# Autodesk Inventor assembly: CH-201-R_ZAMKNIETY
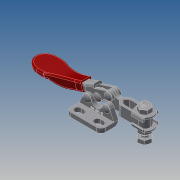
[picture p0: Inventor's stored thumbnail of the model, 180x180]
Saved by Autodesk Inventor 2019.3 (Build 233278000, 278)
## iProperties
Company: ·L?¤¤?
Created: 2010-06
Part Number: CH-201-R_ZAMKNIETY
Material: Ogólny
Description: STEP AP203
Document SubType Name: Assembly
Designer: CADENGINEERING4
Sending System: SolidWorks 2005179
Preprocessor: SwSTEP 2.0
Title: CH-201-R.STEP
Author: ·L?¥Î?
Revision Number: ANY
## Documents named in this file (9)
- E:\STRONA\Horizontal toggle clamp\CH-201-R\CH-201-R_ZAMKNIETY.iam
- E:\STRONA\Horizontal toggle clamp\CH-201-R\201-02___.ipt
- E:\STRONA\Horizontal toggle clamp\CH-201-R\201-06___.ipt
- E:\STRONA\Horizontal toggle clamp\CH-201-R\CH-SA-042007___.ipt
- E:\STRONA\Horizontal toggle clamp\CH-201-R\M4___.ipt
- E:\STRONA\Horizontal toggle clamp\CH-201-R\201-A-04___.ipt
- E:\STRONA\Horizontal toggle clamp\CH-201-R\CH-FW-080___.ipt
- E:\STRONA\Horizontal toggle clamp\CH-201-R\201-R-01___.ipt
- E:\STRONA\Horizontal toggle clamp\CH-201-R\201-03___.iam
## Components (14 placed, 14 different names)
1. 201-02_??_1 — Równoległe:1, Zestawiające:5, Zestawiające:7, Zestawiające:9, Zestawiające:25, Zestawiające:26, Zestawiające:27
2. 201-06_??_2 — Zestawiające:19, Zestawiające:20
3. CH-SA-042007_??_3 — Równoległe:2, Zestawiające:1, Zestawiające:2, Zestawiające:3, Zestawiające:4, Zestawiające:9
4. 201-06_??_4 — Zestawiające:15, Zestawiające:16
5. M4_??_5 — Równoległe:2, Zestawiające:2, Zestawiające:6
6. 201-A-04_??_6 — Zestawiające:10, Zestawiające:11, Zestawiające:12, Zestawiające:13, Zestawiające:18
7. CH-FW-080_??_7 — Równoległe:1, Równoległe:3, Zestawiające:1, Zestawiające:5, Zestawiające:6
8. M4_??_8 — Zestawiające:4, Zestawiające:8
9. 201-06_??_9 — Zestawiające:23, Zestawiające:24, Zestawiające:26
10. CH-FW-080_??_10 — Równoległe:3, Zestawiające:3, Zestawiające:7, Zestawiające:8
11. 201-R-01_??_11 — Zestawiające:13, Zestawiające:14, Zestawiające:16, Zestawiające:23, Zestawiające:24, Zestawiające:25, Przejściowe:1
12. 201-06_??_12 — Zestawiające:21, Zestawiające:22, Zestawiające:27
13. 201-A-04_??_13 — Zestawiające:10, Zestawiające:11, Zestawiające:12, Zestawiające:14, Zestawiające:15, Zestawiające:17
14. 201-03_??_14 [sub-assembly] — Zestawiające:17, Zestawiające:18, Zestawiające:19, Zestawiające:20, Zestawiające:21, Zestawiające:22, Przejściowe:1
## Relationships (31: Mate 27, Flush 3, Transitional 1)
- Równoległe:1 [Flush]: 201-02_??_1 ↔ CH-FW-080_??_7
- Równoległe:2 [Flush]: CH-SA-042007_??_3 ↔ M4_??_5
- Równoległe:3 [Flush]: CH-FW-080_??_7 ↔ CH-FW-080_??_10
- Zestawiające:1 [Mate]: CH-SA-042007_??_3 ↔ CH-FW-080_??_7
- Zestawiające:2 [Mate]: CH-SA-042007_??_3 ↔ M4_??_5
- Zestawiające:3 [Mate]: CH-SA-042007_??_3 ↔ CH-FW-080_??_10
- Zestawiające:4 [Mate]: CH-SA-042007_??_3 ↔ M4_??_8
- Zestawiające:5 [Mate]: 201-02_??_1 ↔ CH-FW-080_??_7
- Zestawiające:6 [Mate]: M4_??_5 ↔ CH-FW-080_??_7
- Zestawiające:7 [Mate]: 201-02_??_1 ↔ CH-FW-080_??_10
- Zestawiające:8 [Mate]: M4_??_8 ↔ CH-FW-080_??_10
- Zestawiające:9 [Mate]: 201-02_??_1 ↔ CH-SA-042007_??_3
- Zestawiające:10 [Mate]: 201-A-04_??_6 ↔ 201-A-04_??_13
- Zestawiające:11 [Mate]: 201-A-04_??_6 ↔ 201-A-04_??_13
- Zestawiające:12 [Mate]: 201-A-04_??_6 ↔ 201-A-04_??_13
- Zestawiające:13 [Mate]: 201-A-04_??_6 ↔ 201-R-01_??_11
- Zestawiające:14 [Mate]: 201-R-01_??_11 ↔ 201-A-04_??_13
- Zestawiające:15 [Mate]: 201-06_??_4 ↔ 201-A-04_??_13
- Zestawiające:16 [Mate]: 201-06_??_4 ↔ 201-R-01_??_11
- Zestawiające:17 [Mate]: 201-A-04_??_13 ↔ 201-03_??_14
- Zestawiające:18 [Mate]: 201-A-04_??_6 ↔ 201-03_??_14
- Zestawiające:19 [Mate]: 201-06_??_2 ↔ 201-03_??_14
- Zestawiające:20 [Mate]: 201-06_??_2 ↔ 201-03_??_14
- Zestawiające:21 [Mate]: 201-06_??_12 ↔ 201-03_??_14
- Zestawiające:22 [Mate]: 201-06_??_12 ↔ 201-03_??_14
- Zestawiające:23 [Mate]: 201-06_??_9 ↔ 201-R-01_??_11
- Zestawiające:24 [Mate]: 201-06_??_9 ↔ 201-R-01_??_11
- Zestawiające:25 [Mate]: 201-02_??_1 ↔ 201-R-01_??_11
- Zestawiające:26 [Mate]: 201-02_??_1 ↔ 201-06_??_9
- Zestawiające:27 [Mate]: 201-02_??_1 ↔ 201-06_??_12
- Przejściowe:1 [Transitional]: 201-R-01_??_11 ↔ 201-03_??_14
